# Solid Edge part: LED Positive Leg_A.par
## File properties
Document Number: P
Revision: A
Title: LED Positive Leg
Author: NMH
Template: iso metric part.par
Last saved by: NMH
Revision: 6
Application: Solid Edge
Username: NMH
Accuracy: 0.990
Rev B: B
Rev B Text: -
Rev B Date: -
Rev C: C
Rev C Text: -
Rev C Date: -
Rev D: D
Rev D Text: -
Rev D Date: -
Part Number: -
Profile: -
Casting: -
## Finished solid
Body 1: solid body, 17 faces, 45 edges, 30 vertices.
  Faces by surface: plane 13, cylinder 4
  Edges by curve: line 37, circle 8
Bounding box of the edges (mm): 1.505 x 0.410 x 22.000, from (-1, -0.205, -20) to (0.505, 0.205, 2).
Cylindrical faces by radius (mm): R0.1 x4
Planar faces by outward normal: +x 3, +y 1, +z 1, -x 4, -y 1, -z 2, oblique 1
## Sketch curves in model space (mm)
line (0.505, -0.205, -4.5999) -> (-0.095, -0.205, -4.5999)
line (-0.095, -0.205, -5.8001) -> (0.505, -0.205, -5.8001)
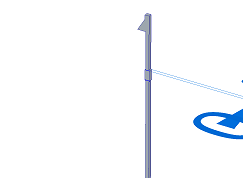
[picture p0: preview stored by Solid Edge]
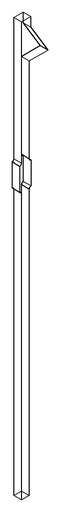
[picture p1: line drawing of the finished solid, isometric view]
